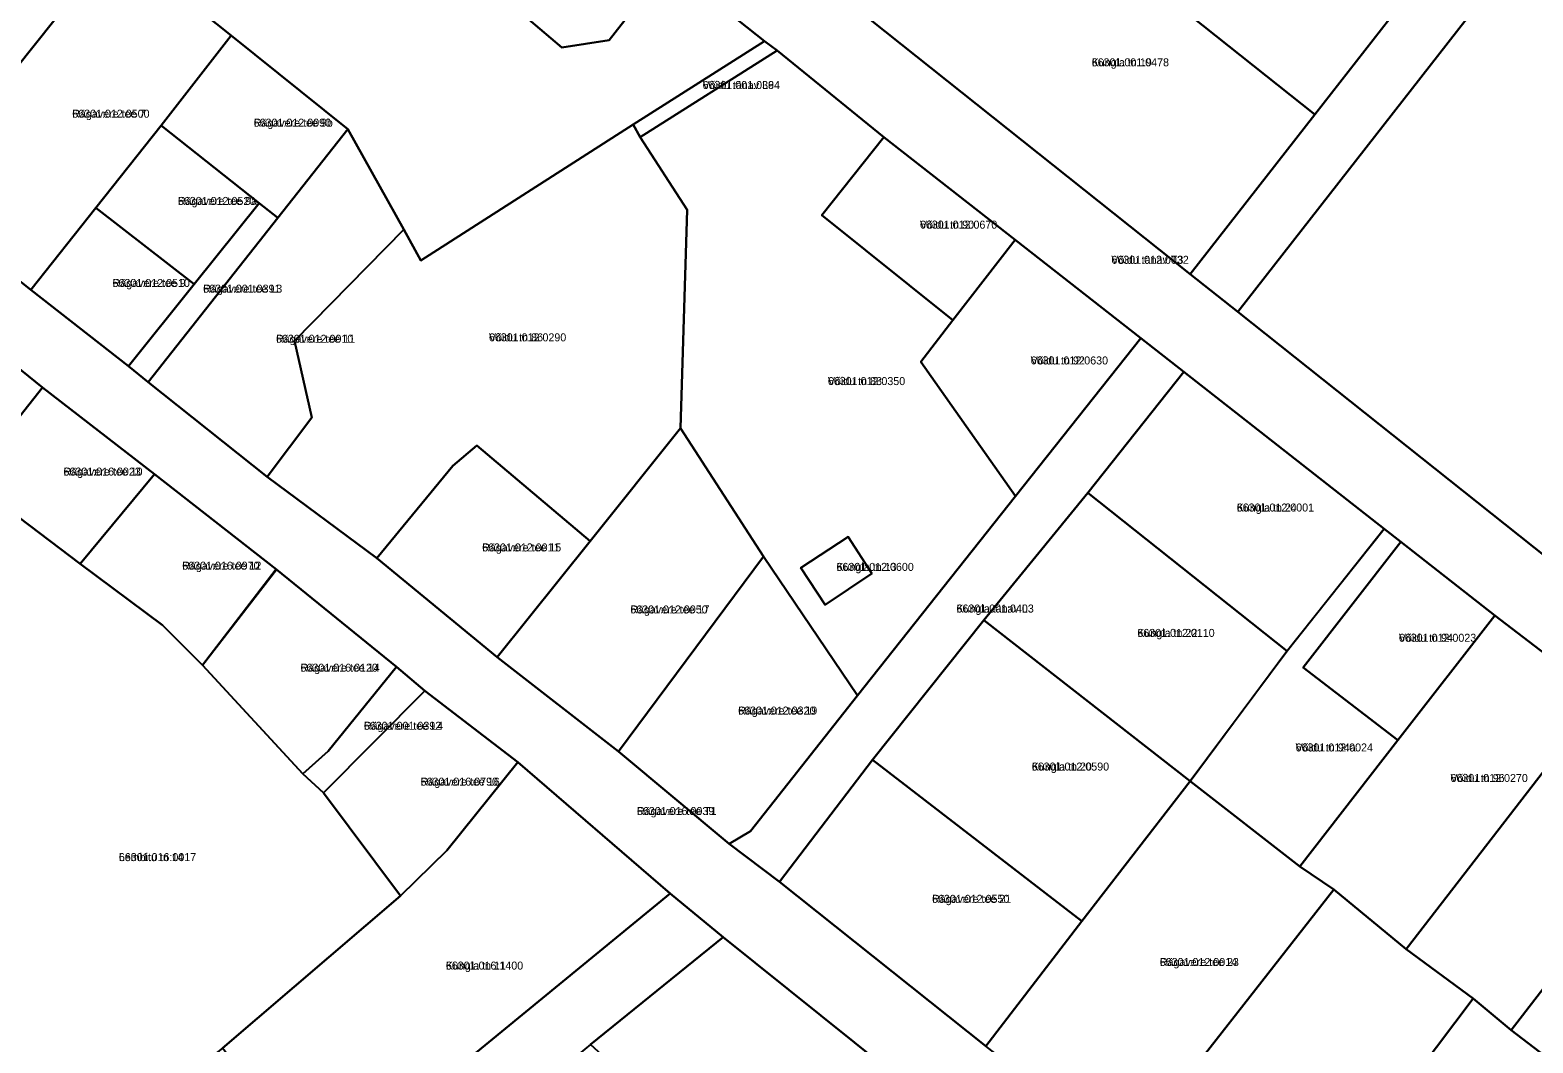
# Model space of a CAD drawing. Extents: x 632278 to 636344, y 6578401 to 6583362.
# Drawn here: x 634837.7 to 635119.5, y 6580768.1 to 6580958 of the extents above; entities that cross this region are included whole.
import ezdxf

# ---------------------------------------------------------------- set-up
doc = ezdxf.new("R2010")
doc.units = 0
for name, color, linetype in [('L_AADRESS', 7, 'Continuous'), ('PIIR', 7, 'Continuous'), ('TUNNUS', 7, 'Continuous')]:
    doc.layers.add(name, color=color, linetype=linetype)

msp = doc.modelspace()

# ---------------------------------------------------------------- linework, layer by layer
at = {"layer": 'PIIR'}
for points in [[(634822.93, 6581096.59), (634855, 6581071.36), (634874.93, 6581055.45), (634877.49, 6581053.44), (634900.78, 6581036.03), (634923.95, 6581016.73), (634941.76, 6581002.89), (634945.82, 6580999.55), (634968.82, 6580981.35), (634987.94, 6580966.28), (634995.29, 6580959.95), (635055.23, 6580912.22), (635064.19, 6580905.18), (635148.77, 6580837.91), (635156.38, 6580831.87), (635270.51, 6580741.99)], [(635262.41, 6580731.79), (635191.38, 6580787.53), (635172.4, 6580802.21), (635167.86, 6580805.69), (635151.82, 6580817.9), (635132.3, 6580833.01), (635112.35, 6580848.22), (635094.77, 6580862.04), (635091.62, 6580864.51), (635054.05, 6580893.93), (635045.98, 6580900.27), (635022.45, 6580918.7), (634997.82, 6580937.94), (634977.82, 6580954.21), (634975.46, 6580955.95), (634957.35, 6580970.29), (634950.06, 6580976.06), (634937.98, 6580985.51), (634934.98, 6580987.7), (634903.28, 6581012.64), (634847.95, 6581056.76), (634813.01, 6581084.53)], [(634815.84, 6580926.73), (634837.9, 6580909.32), (634856.18, 6580895.02), (634859.86, 6580891.99), (634882.2, 6580874.27), (634902.77, 6580859.02), (634925.31, 6580840.41), (634948.09, 6580822.73), (634968.81, 6580805.46), (634978.25, 6580798.29), (635016.95, 6580767.52)], [(634998.34, 6580763.36), (634967.68, 6580787.95), (634957.76, 6580796.1), (634929.16, 6580820.76), (634911.77, 6580834.12), (634906.43, 6580838.62), (634883.91, 6580856.86), (634861.06, 6580874.76), (634840.08, 6580891.01), (634830.79, 6580898.44)]]:
    msp.add_lwpolyline(points, dxfattribs=at)
for points in [[(635055.23, 6580912.22), (635078.63, 6580942.2), (635098.91, 6580968.26), (635119.24, 6580994.25), (635124.71, 6581001.23), (635141.35, 6581018.03), (635150.67, 6581023.97), (635156.7, 6581027.77), (635176.39, 6581040.35), (635202.1, 6581056.83), (635209.39, 6581047.9), (635185.68, 6581032.75), (635160.13, 6581016.49), (635148.57, 6581009.1), (635133.75, 6580994.18), (635127.71, 6580986.57), (635064.19, 6580905.18)], [(634875.44, 6580957), (634853.77, 6580974.29), (634850.41, 6580976.85), (634903.28, 6581012.64), (634934.98, 6580987.7), (634920.94, 6580968.79), (634937.47, 6580954.77), (634946.29, 6580956.14), (634957.35, 6580970.29), (634975.46, 6580955.95), (634950.81, 6580940.29), (634911.03, 6580914.84), (634907.81, 6580920.62), (634897.33, 6580939.45)], [(634831.74, 6580991), (634850.41, 6580976.85), (634853.77, 6580974.29), (634815.84, 6580926.73), (634794.1, 6580943.95)], [(634995.29, 6580959.95), (635018.27, 6580990.22), (635048.49, 6580966.2), (635078.63, 6580942.2), (635055.23, 6580912.22)], [(635048.49, 6580966.2), (635069.02, 6580992), (635098.91, 6580968.26), (635078.63, 6580942.2)], [(634934.98, 6580987.7), (634937.98, 6580985.51), (634950.06, 6580976.06), (634957.35, 6580970.29), (634946.29, 6580956.14), (634937.47, 6580954.77), (634920.94, 6580968.79)], [(635127.71, 6580986.57), (635212.9, 6580920.1), (635148.77, 6580837.91), (635064.19, 6580905.18)], [(634815.84, 6580926.73), (634853.77, 6580974.29), (634875.44, 6580957), (634862.3, 6580940.1), (634850.08, 6580924.68), (634837.9, 6580909.32)], [(634884.19, 6580922.8), (634880.68, 6580925.57), (634862.3, 6580940.1), (634875.44, 6580957), (634897.33, 6580939.45)], [(634950.81, 6580940.29), (634975.46, 6580955.95), (634977.82, 6580954.21), (634952.14, 6580937.96)], [(634975.25, 6580859.32), (634959.7, 6580883.36), (634960.95, 6580924.33), (634952.14, 6580937.96), (634977.82, 6580954.21), (634997.82, 6580937.94), (634986.19, 6580923.32), (635010.78, 6580903.61), (635004.73, 6580895.79), (635022.49, 6580870.6), (634992.88, 6580833.25)], [(634862.3, 6580940.1), (634880.68, 6580925.57), (634868.48, 6580910.36), (634850.08, 6580924.68)], [(634859.86, 6580891.99), (634884.19, 6580922.8), (634897.33, 6580939.45), (634907.81, 6580920.62), (634887.31, 6580899.77), (634890.57, 6580885.35), (634882.2, 6580874.27)], [(634917, 6580876.29), (634902.77, 6580859.02), (634882.2, 6580874.27), (634890.57, 6580885.35), (634887.31, 6580899.77), (634907.81, 6580920.62), (634911.03, 6580914.84), (634950.81, 6580940.29), (634952.14, 6580937.96), (634960.95, 6580924.33), (634959.7, 6580883.36), (634942.75, 6580862.18), (634921.53, 6580880.11)], [(634997.82, 6580937.94), (635022.45, 6580918.7), (635010.78, 6580903.61), (634986.19, 6580923.32)], [(634856.18, 6580895.02), (634868.48, 6580910.36), (634880.68, 6580925.57), (634884.19, 6580922.8), (634859.86, 6580891.99)], [(634850.08, 6580924.68), (634868.48, 6580910.36), (634856.18, 6580895.02), (634837.9, 6580909.32)], [(635004.73, 6580895.79), (635010.78, 6580903.61), (635022.45, 6580918.7), (635045.98, 6580900.27), (635022.49, 6580870.6)], [(634968.81, 6580805.46), (634972.83, 6580807.79), (634992.88, 6580833.25), (635022.49, 6580870.6), (635045.98, 6580900.27), (635054.05, 6580893.93), (635036.07, 6580871.25), (635016.57, 6580847.4), (634995.71, 6580821.21), (634978.25, 6580798.29)], [(634735.93, 6580814.56), (634757.86, 6580828.79), (634765.17, 6580833.42), (634797.02, 6580854.15), (634810.45, 6580870.42), (634830.79, 6580898.44), (634840.08, 6580891.01), (634835.86, 6580885.68), (634830.65, 6580878.99), (634823.64, 6580869.94), (634823.24, 6580869.23), (634803.09, 6580842.19), (634791.25, 6580834.56), (634779.94, 6580827.16), (634758, 6580813.21), (634747.76, 6580806.49), (634746.49, 6580805.11)], [(635054.05, 6580893.93), (635091.62, 6580864.51), (635073.41, 6580841.56), (635036.07, 6580871.25)], [(634840.08, 6580891.01), (634861.06, 6580874.76), (634847.15, 6580857.94), (634831.8, 6580869.51), (634828.29, 6580865.31), (634823.24, 6580869.23), (634823.64, 6580869.94), (634830.65, 6580878.99), (634835.86, 6580885.68)], [(634975.25, 6580859.32), (634948.09, 6580822.73), (634925.31, 6580840.41), (634942.75, 6580862.18), (634959.7, 6580883.36)], [(634902.77, 6580859.02), (634917, 6580876.29), (634921.53, 6580880.11), (634942.75, 6580862.18), (634925.31, 6580840.41)], [(634847.15, 6580857.94), (634861.06, 6580874.76), (634883.91, 6580856.86), (634883.7, 6580856.68), (634870.06, 6580838.92), (634862.57, 6580846.46)], [(634823.24, 6580869.23), (634828.29, 6580865.31), (634831.8, 6580869.51), (634847.15, 6580857.94), (634862.57, 6580846.46), (634870.06, 6580838.92), (634888.87, 6580818.57), (634892.77, 6580814.98), (634907.16, 6580795.65), (634873.8, 6580767.13), (634843.07, 6580742.91), (634840.06, 6580746.68), (634822.92, 6580768.08), (634819.98, 6580772.06), (634822.28, 6580774.15), (634815.33, 6580782.85), (634813.98, 6580781.78), (634811.16, 6580779.56), (634801.59, 6580792.39), (634802.72, 6580793.42), (634817.17, 6580805.59), (634823.5, 6580810.97), (634823.96, 6580814.19), (634803.09, 6580842.19)], [(635055.26, 6580817.21), (635016.57, 6580847.4), (635036.07, 6580871.25), (635073.41, 6580841.56)], [(635091.62, 6580864.51), (635094.77, 6580862.04), (635076.41, 6580838.5), (635094.19, 6580824.85), (635075.83, 6580801.21), (635055.26, 6580817.21), (635073.32, 6580841.52)], [(634995.54, 6580856.11), (634991.11, 6580862.99), (634982.27, 6580857.17), (634986.84, 6580850.24)], [(634995.54, 6580856.11), (634986.84, 6580850.24), (634982.27, 6580857.17), (634991.11, 6580862.99)], [(635094.77, 6580862.04), (635112.35, 6580848.22), (635094.19, 6580824.85), (635076.41, 6580838.5)], [(634968.81, 6580805.46), (634948.09, 6580822.73), (634975.25, 6580859.32), (634992.88, 6580833.25), (634972.83, 6580807.79)], [(634906.43, 6580838.62), (634893.65, 6580822.79), (634888.87, 6580818.57), (634870.06, 6580838.92), (634883.91, 6580856.86)], [(635016.57, 6580847.4), (635055.26, 6580817.21), (635034.95, 6580790.95), (634995.71, 6580821.21)], [(635132.3, 6580833.01), (635095.73, 6580785.69), (635082.16, 6580796.88), (635075.83, 6580801.21), (635094.19, 6580824.85), (635112.35, 6580848.22)], [(634906.43, 6580838.62), (634911.77, 6580834.12), (634892.77, 6580814.98), (634888.87, 6580818.57), (634893.65, 6580822.79)], [(634929.16, 6580820.76), (634915.86, 6580804.18), (634907.16, 6580795.65), (634892.77, 6580814.98), (634911.77, 6580834.12)], [(635108.29, 6580776.43), (635095.73, 6580785.69), (635132.3, 6580833.01), (635151.82, 6580817.9), (635133.61, 6580794.06), (635115.42, 6580770.48)], [(634995.71, 6580821.21), (635034.95, 6580790.95), (635016.95, 6580767.52), (634978.25, 6580798.29)], [(634873.8, 6580767.13), (634907.16, 6580795.65), (634915.86, 6580804.18), (634929.16, 6580820.76), (634957.76, 6580796.1), (634892.88, 6580742.94)], [(635055.26, 6580817.21), (635075.83, 6580801.21), (635082.16, 6580796.88), (635043.23, 6580747.12), (635016.95, 6580767.52), (635034.95, 6580790.95)], [(635115.42, 6580770.48), (635133.61, 6580794.06), (635149.52, 6580782.11), (635167.86, 6580805.69), (635172.4, 6580802.21), (635135.9, 6580754.85)], [(634832.82, 6580695.01), (634892.88, 6580742.94), (634957.76, 6580796.1), (634967.68, 6580787.95), (634942.84, 6580767.78), (634929.01, 6580756.42), (634915.67, 6580745.14), (634907.44, 6580738.83), (634874.12, 6580712.08), (634840.98, 6580685.48)], [(635043.23, 6580747.12), (635082.16, 6580796.88), (635095.73, 6580785.69), (635108.29, 6580776.43), (635070.3, 6580725.98)], [(634942.84, 6580767.78), (634967.68, 6580787.95), (634998.34, 6580763.36), (634977.26, 6580736.66), (634965.61, 6580746.87)], [(635070.3, 6580725.98), (635108.29, 6580776.43), (635115.42, 6580770.48), (635135.9, 6580754.85), (635099.43, 6580707.69)]]:
    msp.add_lwpolyline(points, close=True, dxfattribs=at)

# ---------------------------------------------------------------- texts
at = {"layer": 'L_AADRESS'}
for s, p in [('Kungla tn 19', (635036.78, 6580951.22)), ('Võidu tänav L6', (634963.83, 6580946.96)), ('Rägavere tee 7', (634845.64, 6580941.59)), ('Rägavere tee 9b', (634879.66, 6580939.9)), ('Rägavere tee 9a', (634865.46, 6580925.23)), ('Võidu tn 90', (635004.58, 6580920.78)), ('Võidu tänav T3', (635040.48, 6580914.19)), ('Rägavere tee 9', (634853.2, 6580909.85)), ('Rägavere tee L3', (634870.18, 6580908.78)), ('Rägavere tee 11', (634883.84, 6580899.39)), ('Võidu tn 86', (634923.77, 6580899.65)), ('Võidu tn 92', (635025.35, 6580895.32)), ('Võidu tn 88', (634987.32, 6580891.45)), ('Rägavere tee 10', (634843.99, 6580874.48)), ('Kungla tn 24', (635063.98, 6580867.74)), ('Rägavere tee 15', (634922.5, 6580860.26)), ('Rägavere tee 12', (634866.26, 6580856.84)), ('Kungla tn 13', (634988.93, 6580856.61)), ('Rägavere tee 17', (634950.28, 6580848.63)), ('Kungla tänav L3', (635011.43, 6580848.8)), ('Kungla tn 22', (635045.34, 6580844.23)), ('Võidu tn 94', (635094.38, 6580843.32)), ('Rägavere tee 14', (634888.44, 6580837.71)), ('Rägavere tee 19', (634970.49, 6580829.67)), ('Rägavere tee L4', (634900.32, 6580826.82)), ('Võidu tn 94a', (635075.02, 6580822.75)), ('Kungla tn 20', (635025.55, 6580819.17)), ('Võidu tn 96', (635104.06, 6580817.02)), ('Rägavere tee 16', (634910.96, 6580816.34)), ('Rägavere tee T1', (634951.52, 6580810.83)), ('Lembitu tn 14', (634854.38, 6580802.19)), ('Rägavere tee 21', (635006.85, 6580794.37)), ('Kungla tn 11', (634915.69, 6580781.85)), ('Rägavere tee 23', (635049.55, 6580782.52))]:
    msp.add_text(s, height=1.5, dxfattribs=at).set_placement(p)
at = {"layer": 'TUNNUS'}
for s, p in [('66301:001:0478', (635036.78, 6580951.22)), ('66301:001:0394', (634963.83, 6580946.96)), ('66301:012:0500', (634845.64, 6580941.59)), ('66301:012:0090', (634879.66, 6580939.9)), ('66301:012:0520', (634865.46, 6580925.23)), ('66301:012:0670', (635004.58, 6580920.78)), ('66301:012:0032', (635040.48, 6580914.19)), ('66301:012:0510', (634853.2, 6580909.85)), ('66301:001:0391', (634870.18, 6580908.78)), ('66301:012:0010', (634883.84, 6580899.39)), ('66301:012:0290', (634923.77, 6580899.65)), ('66301:012:0630', (635025.35, 6580895.32)), ('66301:012:0350', (634987.32, 6580891.45)), ('66301:016:0023', (634843.99, 6580874.48)), ('66301:012:0001', (635063.98, 6580867.74)), ('66301:012:0011', (634922.5, 6580860.26)), ('66301:016:0970', (634866.26, 6580856.84)), ('66301:012:0600', (634988.93, 6580856.61)), ('66301:012:0050', (634950.28, 6580848.63)), ('66301:001:0403', (635011.43, 6580848.8)), ('66301:012:0110', (635045.34, 6580844.23)), ('66301:012:0023', (635094.38, 6580843.32)), ('66301:016:0120', (634888.44, 6580837.71)), ('66301:012:0320', (634970.49, 6580829.67)), ('66301:001:0392', (634900.32, 6580826.82)), ('66301:012:0024', (635075.02, 6580822.75)), ('66301:012:0590', (635025.55, 6580819.17)), ('66301:012:0270', (635104.06, 6580817.02)), ('66301:016:0790', (634910.96, 6580816.34)), ('66301:016:0039', (634951.52, 6580810.83)), ('66301:016:0017', (634854.38, 6580802.19)), ('66301:012:0550', (635006.85, 6580794.37)), ('66301:016:1400', (634915.69, 6580781.85)), ('66301:012:0014', (635049.55, 6580782.52))]:
    msp.add_text(s, height=1.5, dxfattribs=at).set_placement(p)

doc.saveas('drawing.dxf')
